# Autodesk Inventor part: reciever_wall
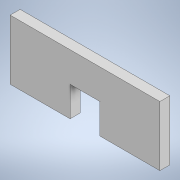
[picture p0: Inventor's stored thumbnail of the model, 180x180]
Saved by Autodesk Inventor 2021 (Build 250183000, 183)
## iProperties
Created: 2026-10
Part Number: reciever_wall
Material: Generic
Document SubType Name: Modeling
Designer: alolo
Density: 1 g/cm^3
Appearance: Default
Author: alolo
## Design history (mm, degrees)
sketch "Sketch1"
  geometry: L1 (0, 0)-(75, 0); L2 (75, 0)-(75, 30); L3 (75, 30)-(0, 30); L4 (0, 30)-(0, 0); L5 (30, 0)-(45, 0); L6 (45, 0)-(45, 15); L7 (45, 15)-(30, 15); L8 (30, 15)-(30, 0); 4 further points
  constraints: 16 end point, 4 parallel, 2 horizontal, 2 midpoint, 2 perpendicular, 1 coincident, 1 point on line, 1 vertical alignment
  dimensions: "d0" = 75 distance of L3.end L2.end; "d1" = 30 distance of L3.end L1.start; "d2" = 15 distance of L7.end L6.end; "d3" = 15 distance of L6.end L5.end
extrude "Extrusion1" new body sketch "Sketch1" distance "d4" = 5 (= wood_thickness); taper "d5" = 0 deg
body "Solid1"
other parameters: "slide_length" = 195 [user parameter], "slide_angle" = 7 deg [user parameter], "slide_width" = 65 [user parameter], "wood_thickness" = 5 [user parameter; used in 1 equation term], "aclyric_thickness" = 6 [user parameter]
